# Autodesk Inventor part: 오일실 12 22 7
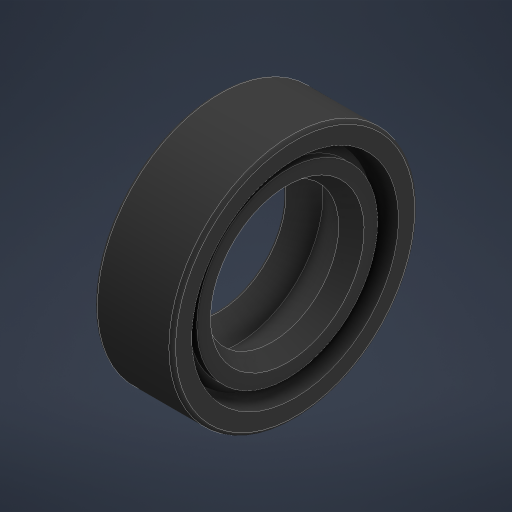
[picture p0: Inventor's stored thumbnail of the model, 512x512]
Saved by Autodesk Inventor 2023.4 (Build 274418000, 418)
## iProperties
Created: 2024-05
Part Number: 오일실 12 22 7
Material: 고무
Description: 오일-실
Document SubType Name: Modeling
Designer: Edu03
Density: 0.93 g/cm^3
Appearance: 기본값
Sending System: Autodesk Inventor 2025
Preprocessor: ST-DEVELOPER v20
Author: jhkim
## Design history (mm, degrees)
node "오일실 12 22 71"
node "솔리드1"
body "Solid1"
